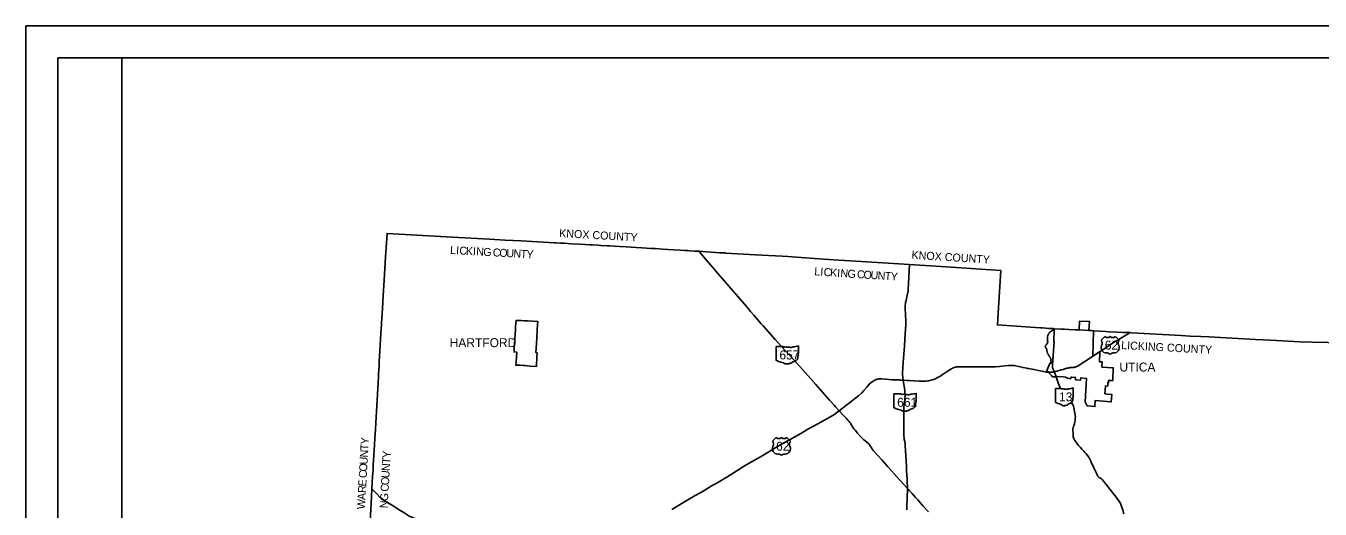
# Model space of a CAD drawing. Extents: x 1853412 to 2125412, y 679418 to 855418.
# Drawn here: x 1853412 to 2015090, y 795017 to 855418 of the extents above; entities that cross this region are included whole.
import ezdxf

# ---------------------------------------------------------------- set-up
doc = ezdxf.new("R2010")
doc.units = 0
for name, color, linetype in [('GM_X_Corporation', 7, 'Continuous'), ('GM_X_Corporation_Text', 7, 'Continuous'), ('GM_X_County', 7, 'Continuous'), ('GM_X_County_Text', 7, 'Continuous'), ('GM_X_State_Location', 7, 'Continuous'), ('GM_X_State_Route', 7, 'Continuous'), ('GM_X_State_Shield', 7, 'Continuous'), ('GM_X_US_Location', 7, 'Continuous'), ('GM_X_US_Route', 7, 'Continuous'), ('GM_X_US_Shield', 7, 'Continuous'), ('SH_Border', 7, 'Continuous'), ('SH_Cut_Line', 7, 'Continuous'), ('UT_P_Electric', 7, 'Continuous')]:
    doc.layers.add(name, color=color, linetype=linetype)

msp = doc.modelspace()

# ---------------------------------------------------------------- linework, layer by layer
at = {"layer": 'GM_X_Corporation'}
for points in [[(1914724, 814655), (1914398, 814673), (1914412, 814947), (1914420, 815224), (1914432, 815606), (1914531, 816947), (1914563, 817386), (1914595, 817823), (1914651, 818601), (1914704, 818599), (1915130, 818580), (1915208, 818576), (1915270, 818573), (1915679, 818555), (1916069, 818537), (1917358, 818478), (1917357, 818463), (1917331, 818109), (1917296, 817447), (1917280, 817170), (1917267, 816962), (1917256, 816776), (1917238, 816462), (1917230, 816341), (1917224, 816233), (1917223, 816217), (1917207, 815951), (1917187, 815616), (1917186, 815591), (1917184, 815559), (1917170, 815331), (1917162, 815184), (1917154, 815065), (1917125, 814574), (1917279, 814563), (1917277, 814507), (1917257, 814106), (1917189, 812840), (1916411, 812900), (1916348, 812905), (1915789, 812949), (1915630, 812964), (1915571, 812970), (1915140, 813012), (1915128, 812993), (1914613, 813031), (1914668, 813436)], [(1981154, 816897), (1981175, 816939), (1981192, 816964), (1981206, 816983), (1981238, 817017), (1981301, 817081), (1981398, 817177), (1981452, 817228), (1981492, 817262), (1981605, 817331), (1981628, 817344), (1981652, 817357), (1981715, 817381), (1981730, 817388), (1981736, 817397), (1981738, 817405), (1981741, 817412), (1981746, 817433), (1981742, 817466), (1981740, 817480), (1981743, 817496), (1981744, 817501), (1981746, 817515), (1981750, 817533), (1981752, 817543), (1981756, 817574), (1981870, 817569), (1983126, 817503), (1983702, 817463), (1984529, 817426), (1984709, 817415), (1984840, 817408), (1984978, 817400), (1984978, 817406), (1984970, 817421), (1985045, 818514), (1986261, 818487), (1986194, 817351), (1986529, 817328), (1986784, 817315), (1986701, 814154), (1987449, 814626), (1987568, 814701), (1987524, 813441), (1987877, 813412), (1987824, 812777), (1989249, 812678), (1989179, 811086), (1988663, 811098), (1988656, 810796), (1988626, 810826), (1988581, 810867), (1988556, 810393), (1988261, 810409), (1988203, 809429), (1988528, 809401), (1989066, 809354), (1989007, 808427), (1987000, 808604), (1986961, 807841), (1985997, 807925), (1985725, 808427), (1985892, 811352), (1985184, 811418), (1985168, 811140), (1984520, 811185), (1984536, 811454), (1984092, 811492), (1983949, 811505), (1983939, 811313), (1983720, 811361), (1983512, 811406), (1983283, 811517), (1982679, 811593), (1982111, 811563), (1981644, 811563), (1981518, 811702), (1981130, 812128), (1980942, 812333), (1981200, 812912), (1981381, 813302), (1981451, 813249), (1981464, 813380), (1981475, 813465), (1981473, 813485), (1981473, 813511), (1981470, 813528), (1981471, 813550), (1981461, 813613), (1981458, 813738), (1981458, 813755), (1981457, 813781), (1981453, 813802), (1981431, 813856), (1981424, 813873), (1981408, 813902), (1981387, 813936), (1981369, 813964), (1981340, 814006), (1981308, 814050), (1981258, 814123), (1981245, 814143), (1981217, 814189), (1981182, 814240), (1981151, 814292), (1981129, 814332), (1981097, 814386), (1981076, 814426), (1981054, 814466), (1981040, 814501), (1981029, 814528), (1981018, 814557), (1981005, 814586), (1981001, 814599), (1980988, 814633), (1980978, 814671), (1980976, 814676), (1980975, 814709), (1980973, 814725), (1980972, 814734), (1980966, 814781), (1980962, 814795), (1980960, 814803), (1980960, 814812), (1980959, 814847), (1980955, 814868), (1980955, 814871), (1980950, 814918), (1980944, 814953), (1980937, 814985), (1980930, 815003), (1980907, 815043), (1980897, 815056), (1980874, 815090), (1980857, 815111), (1980820, 815166), (1980790, 815216), (1980778, 815239), (1980769, 815264), (1980762, 815290), (1980760, 815303), (1980759, 815324), (1980759, 815344), (1980761, 815357), (1980765, 815372), (1980773, 815389), (1980784, 815406), (1980794, 815417), (1980818, 815456), (1980827, 815471), (1980858, 815512), (1980885, 815543), (1980926, 815602), (1980964, 815657), (1980979, 815678), (1980993, 815696), (1981001, 815709), (1981005, 815716), (1981013, 815737), (1981034, 815819), (1981057, 815897), (1981060, 815917), (1981060, 815938), (1981058, 815950), (1981057, 815959), (1981054, 815969), (1981049, 815983), (1981021, 816075), (1981017, 816136), (1981022, 816335), (1981027, 816546), (1981075, 816700), (1981082, 816723), (1981120, 816822), (1981138, 816864)]]:
    msp.add_lwpolyline(points, close=True, dxfattribs=at)
at = {"layer": 'GM_X_County'}
msp.add_lwpolyline([(1896383, 792786), (1896549, 795741), (1896640, 797539), (1896644, 797604), (1896728, 799113), (1896776, 799934), (1896815, 800598), (1896841, 801062), (1896877, 801716), (1896960, 803042), (1897014, 803893), (1897037, 804352), (1897400, 810815), (1897451, 811579), (1897480, 811933), (1897539, 812985), (1897563, 813419), (1897622, 814815), (1897736, 816950), (1897821, 818182), (1897828, 818257), (1897947, 820093), (1898047, 821707), (1898127, 823010), (1898165, 823653), (1898352, 826534), (1898387, 827092), (1898530, 829468), (1903006, 829212), (1906703, 828996), (1911340, 828742), (1913287, 828636), (1915271, 828536), (1919433, 828302), (1919668, 828292), (1920206, 828267), (1920580, 828244), (1920653, 828242), (1921535, 828187), (1922550, 828131), (1923280, 828086), (1923869, 828056), (1924212, 828035), (1924884, 827998), (1925241, 827975), (1926021, 827928), (1926322, 827910), (1927588, 827835), (1928412, 827800), (1929657, 827724), (1930354, 827679), (1930920, 827644), (1931539, 827608), (1932012, 827584), (1932937, 827525), (1933609, 827479), (1934356, 827436), (1935132, 827380), (1935716, 827350), (1936120, 827325), (1936311, 827314), (1936924, 827276), (1937532, 827240), (1937968, 827208), (1938444, 827185), (1939560, 827107), (1940112, 827070), (1940744, 827034), (1940804, 827028), (1944569, 826800), (1947877, 826620), (1948592, 826572), (1953053, 826265), (1955665, 826095), (1955709, 826088), (1958412, 825906), (1961146, 825748), (1963813, 825576), (1968379, 825285), (1968994, 825253), (1975184, 824851), (1974904, 820238), (1974871, 819560), (1974781, 818037), (1978930, 817778), (1980161, 817683), (1980203, 817671), (1980400, 817660), (1980833, 817636), (1981174, 817614), (1981338, 817602), (1981470, 817591), (1981520, 817588), (1981554, 817584), (1981756, 817574), (1981870, 817569), (1982739, 817527), (1985661, 817385), (1986194, 817351), (1986762, 817321), (1988299, 817219), (1988745, 817193), (1989753, 817138), (1990488, 817100), (1990798, 817083), (1990911, 817079), (1991299, 817080), (1991540, 817069), (1993052, 816987), (1997717, 816726), (1998868, 816656), (2000193, 816596), (2001220, 816537), (2001879, 816525), (2006295, 816254), (2007010, 816217), (2008903, 816117), (2012612, 815941), (2014115, 815904), (2017998, 815808)], dxfattribs=at)
at = {"layer": 'GM_X_State_Route'}
msp.add_line((1963529, 797443), (1963528, 797601), dxfattribs=at)
for points in [[(1955006, 807313), (1954560, 807817), (1954387, 808010), (1953821, 808644), (1952060, 810625), (1951435, 811327), (1950076, 812853), (1948275, 814845), (1947030, 816230), (1945501, 817914), (1945399, 818039), (1945262, 818191), (1944358, 819256), (1943952, 819717), (1943465, 820286), (1939613, 824753), (1939458, 824933), (1938398, 826163), (1937533, 827237)], [(1963430, 821326), (1963513, 821715), (1963605, 822142), (1963616, 822214), (1963623, 822411), (1963814, 825573)], [(1963334, 820969), (1963359, 821073), (1963423, 821290), (1963430, 821326)], [(1962930, 812018), (1963007, 813357), (1963154, 815429), (1963269, 816986), (1963338, 818055), (1963345, 818258), (1963345, 818442), (1963342, 818635), (1963330, 818828), (1963309, 819027), (1963280, 819603), (1963262, 819823), (1963253, 820015), (1963253, 820190), (1963257, 820302), (1963273, 820501), (1963282, 820686), (1963287, 820754), (1963315, 820887), (1963334, 820969)], [(1963019, 811123), (1962930, 811797), (1962927, 811970), (1962930, 812018)], [(1963528, 797601), (1963526, 797833), (1963505, 798311), (1963498, 798778), (1963429, 799811), (1963400, 800374), (1963371, 801045), (1963272, 802908), (1963250, 803167), (1963191, 803475), (1963149, 803715), (1963116, 803909), (1963094, 804165), (1963086, 804336), (1963102, 804880), (1963104, 806015), (1963088, 807602), (1963095, 807755), (1963100, 807877), (1963114, 808065), (1963125, 808195), (1963201, 808708), (1963229, 808914), (1963241, 809183), (1963244, 809304), (1963229, 809552), (1963196, 809878), (1963158, 810111), (1963019, 811123)], [(1963528, 797601), (1962229, 799055), (1961269, 800123), (1961053, 800359), (1960909, 800515), (1960337, 801171), (1959245, 802364), (1959032, 802659), (1958795, 803055), (1958749, 803112), (1958709, 803158), (1958615, 803245), (1958109, 803671), (1957735, 804063), (1957263, 804571), (1957032, 804827), (1956884, 804997), (1956742, 805185), (1956513, 805578), (1956414, 805759), (1956344, 805854), (1956249, 805978), (1956131, 806109), (1955931, 806325), (1955785, 806482), (1955445, 806840), (1955103, 807224), (1955006, 807313)], [(1963459, 794937), (1963468, 795229), (1963509, 796558), (1963529, 797443)], [(1966168, 794673), (1965478, 795440), (1964828, 796167), (1964564, 796455), (1964108, 796961), (1963761, 797359), (1963703, 797422), (1963528, 797601)]]:
    msp.add_lwpolyline(points, dxfattribs=at)
at = {"layer": 'GM_X_State_Shield'}
for p, q in [((1947140, 815305), (1947140, 813604)), ((1947988, 815335), (1947168, 815335)), ((1949942, 814487), (1949942, 815377)), ((1949941, 814487), (1949942, 814487)), ((1982019, 810071), (1982019, 808370)), ((1982697, 810100), (1982041, 810100)), ((1984260, 809252), (1984260, 810142)), ((1961841, 809389), (1961841, 807688)), ((1962689, 809418), (1961869, 809418)), ((1964642, 808571), (1964643, 808570)), ((1964643, 808570), (1964643, 809460)), ((1984260, 809252), (1984260, 809252))]:
    msp.add_line(p, q, dxfattribs=at)
for centre, radius, start, end in [((1982044, 810074), 26, 98.1301, 188.1301), ((1982854, 810297), 252, 231.61951, 271.11188), ((1982937, 809145), 904, 80.48669, 94.98827), ((1983142, 810083), 72.7, 219.79206, 297.10237), ((1983249, 809887), 151, 54.46668, 119.14113), ((1983444, 810156), 182, 233.85621, 294.82819), ((1983765, 809580), 478, 97.34618, 120.76885), ((1983462, 812419), 2377, 275.84447, 288.90645), ((1984235, 810146), 25, 351.86209, 97.738), ((1983595, 808767), 595, 292.30889, 8.98584), ((1984349, 808880), 169, 136.8065, 186.92959), ((1984254, 809187), 38.6, 107.94398, 210.33697), ((1984009, 809074), 232, 340.03296, 23.64957), ((1984233, 809249), 26.7, 289.60381, 7.73413), ((1982045, 808366), 26.2, 171.95839, 258.30661), ((1982049, 808540), 200, 267.33899, 280.60386), ((1982090, 808271), 72.1, 29.74838, 93.27175), ((1983000, 809800), 1716, 240.41292, 257.1985), ((1982488, 807605), 537, 47.18416, 75.83597), ((1983069, 808263), 341, 230.70037, 286.29184), ((1983266, 807675), 280, 85.69512, 111.20995), ((1983291, 808136), 182, 268.77702, 315.54927), ((1983455, 807971), 51.1, 65.75173, 132.64842), ((1983433, 808205), 192, 282.87319, 323.27711), ((1983846, 807892), 326, 94.40312, 142.57675)]:
    msp.add_arc(centre, radius, start, end, dxfattribs=at)
for centre, major_axis, start_param, end_param in [((1947172, 815309), (32.5, 0), 1.7126934, 3.2834897), ((1948183, 815532), (315, 0), 4.042523, 4.731795), ((1948288, 814380), (1130, 0), 1.4047578, 1.6578581), ((1948544, 815318), (90.8, 0), 3.8360951, 5.1854146), ((1948678, 815121), (189, 0), 0.950623, 2.079405), ((1948921, 815391), (227, 0), 4.0815608, 5.1457227), ((1949323, 814815), (598, 0), 1.6990114, 2.1078141), ((1948944, 817654), (2971, 0), 4.8143942, 5.0423688), ((1949911, 815380), (31.2, 0), 6.1411519, 7.9890352), ((1947172, 813600), (32.7, 0), 3.00124, 4.5083009), ((1947177, 813775), (250, 0), 4.6659457, 4.8974612), ((1947228, 813506), (90.1, 0), 0.5192072, 1.6278991), ((1948366, 815034), (2146, 0), 4.1959971, 4.4889607), ((1947726, 812840), (671, 0), 0.8235189, 1.3235874), ((1948730, 813370), (227, 0), 4.6910439, 5.5073738), ((1948935, 813205), (63.9, 0), 1.1475842, 2.3151517), ((1948908, 813439), (240, 0), 4.9370686, 5.64225), ((1949423, 813127), (407, 0), 1.6476453, 2.4884337), ((1949110, 814001), (743, 0), 5.1017525, 6.4400178), ((1950053, 814114), (211, 0), 2.3877238, 3.2625369), ((1949934, 814422), (48.3, 0), 1.8839779, 3.6710726), ((1949627, 814309), (290, 0), 5.9346948, 6.6959481), ((1949908, 814483), (33.4, 0), 5.05454, 6.4181714), ((1948452, 813498), (426, 0), 4.0264811, 4.9967352), ((1948699, 812909), (350, 0), 1.495662, 1.9409797), ((1961873, 809393), (32.5, 0), 1.7126934, 3.2834897), ((1962884, 809616), (315, 0), 4.042523, 4.731795), ((1962989, 808463), (1130, 0), 1.4047578, 1.6578581), ((1963245, 809401), (90.8, 0), 3.8360951, 5.1854146), ((1963379, 809205), (189, 0), 0.950623, 2.079405), ((1963623, 809474), (227, 0), 4.0815608, 5.1457227), ((1964024, 808899), (598, 0), 1.6990114, 2.1078141), ((1963645, 811737), (2971, 0), 4.8143942, 5.0423688), ((1964636, 808505), (48.3, 0), 1.8839779, 3.6710726), ((1964328, 808393), (290, 0), 5.9346948, 6.6959481), ((1964612, 809464), (31.2, 0), 6.1411519, 7.9890352), ((1964609, 808567), (33.4, 0), 5.05454, 6.4181714), ((1961873, 807684), (32.7, 0), 3.00124, 4.5083009), ((1961878, 807858), (250, 0), 4.6659457, 4.8974612), ((1961929, 807590), (90.1, 0), 0.5192072, 1.6278991), ((1963067, 809118), (2146, 0), 4.1959971, 4.4889607), ((1962427, 806923), (671, 0), 0.8235189, 1.3235874), ((1963153, 807581), (426, 0), 4.0264811, 4.9967352), ((1963400, 806993), (350, 0), 1.495662, 1.9409797), ((1963431, 807454), (227, 0), 4.6910439, 5.5073738), ((1963636, 807289), (63.9, 0), 1.1475842, 2.3151517), ((1963609, 807523), (240, 0), 4.9370686, 5.64225), ((1964125, 807210), (407, 0), 1.6476453, 2.4884337), ((1963811, 808085), (743, 0), 5.1017525, 6.4400178), ((1964754, 808198), (211, 0), 2.3877238, 3.2625369)]:
    msp.add_ellipse(centre, major_axis=major_axis, ratio=0.8, start_param=start_param, end_param=end_param, dxfattribs=at)
at = {"layer": 'GM_X_US_Route'}
for points in [[(1987497, 814650), (1988061, 815023), (1988373, 815228), (1988844, 815539), (1989282, 815827), (1989559, 816003), (1989806, 816156), (1990147, 816361), (1990822, 816769), (1991185, 816988), (1991301, 817077)], [(1981852, 812180), (1981922, 812202), (1982034, 812231), (1982202, 812276), (1982739, 812422), (1982984, 812488), (1983343, 812587), (1983459, 812618), (1983587, 812652), (1983686, 812675), (1983776, 812692), (1983881, 812705), (1984015, 812714), (1984217, 812724), (1984315, 812734), (1984410, 812749), (1984501, 812769), (1984586, 812794), (1984695, 812834), (1984774, 812871), (1984862, 812917), (1984961, 812978), (1985135, 813091), (1985381, 813254), (1986137, 813752), (1986462, 813966), (1986528, 814011)], [(1986528, 814011), (1986703, 814128), (1987101, 814387), (1987471, 814632), (1987497, 814650)], [(1963432, 811097), (1963742, 811078), (1964368, 811033), (1964942, 811012), (1965480, 810994), (1965879, 811016), (1966076, 811040), (1966178, 811054), (1966336, 811085), (1966622, 811167), (1966814, 811232), (1967105, 811353), (1967377, 811491), (1967577, 811613), (1967868, 811797), (1968511, 812226), (1968955, 812523), (1969028, 812566), (1969126, 812622), (1969183, 812649), (1969392, 812732), (1969530, 812761), (1969653, 812785), (1969789, 812800), (1970498, 812803), (1971199, 812793), (1972298, 812793), (1973319, 812801), (1974501, 812811), (1975039, 812844), (1975709, 812917), (1976068, 812952)], [(1976068, 812952), (1976094, 812954), (1976413, 812981), (1976630, 812984), (1976898, 812957), (1977605, 812814), (1977983, 812715), (1978439, 812626), (1978585, 812612)], [(1978585, 812612), (1978630, 812603), (1979385, 812451), (1980094, 812310), (1980376, 812240), (1980567, 812202), (1980776, 812164), (1980827, 812155)], [(1980827, 812155), (1980868, 812148), (1980955, 812138), (1981031, 812130)], [(1981031, 812130), (1981036, 812130), (1981131, 812125), (1981289, 812137), (1981438, 812139), (1981598, 812152), (1981705, 812153), (1981852, 812180)], [(1955006, 807313), (1955946, 808058), (1956508, 808489), (1957459, 809234), (1957823, 809535), (1958106, 809836), (1958466, 810256), (1958895, 810748), (1959075, 810897), (1959253, 811028), (1959399, 811103), (1959564, 811177), (1959664, 811211), (1959762, 811240), (1959869, 811264), (1960009, 811292), (1960211, 811298), (1960337, 811297), (1960825, 811250), (1961604, 811189), (1962182, 811168), (1962509, 811162), (1962594, 811156)], [(1962594, 811156), (1963019, 811123), (1963432, 811097)], [(1942849, 800206), (1943484, 800592), (1945185, 801563), (1946020, 802055), (1946570, 802401), (1946765, 802517), (1947092, 802713), (1947307, 802831), (1948255, 803377), (1949325, 803977), (1950409, 804587), (1950617, 804714), (1951115, 804993), (1951636, 805305), (1951725, 805355), (1952331, 805698), (1953861, 806520), (1954049, 806628), (1954332, 806798), (1955006, 807313)], [(1934099, 794969), (1934865, 795428), (1935693, 795938), (1937012, 796723), (1937657, 797051), (1937999, 797266), (1938467, 797542), (1939218, 797992), (1939627, 798234), (1940473, 798728), (1940743, 798895), (1940960, 799017)], [(1940960, 799017), (1942817, 800187), (1942849, 800206)]]:
    msp.add_lwpolyline(points, dxfattribs=at)
at = {"layer": 'GM_X_US_Shield'}
for p, q in [((1988209, 816589), (1987742, 816122)), ((1989983, 816122), (1989516, 816589)), ((1988396, 814534), (1988489, 814534)), ((1989236, 814534), (1989330, 814534)), ((1947146, 803959), (1946679, 803492)), ((1948920, 803492), (1948453, 803959)), ((1947333, 801905), (1947426, 801905)), ((1948173, 801905), (1948267, 801905))]:
    msp.add_line(p, q, dxfattribs=at)
for centre, radius, start, end in [((1988536, 816922), 467, 225.573, 314.427), ((1989189, 816922), 467, 225.573, 314.427), ((1988388, 815188), 654, 154.83192, 270.63826), ((1987206, 815747), 654, 334.54712, 35.00093), ((1989337, 815188), 654, 269.36174, 25.16808), ((1990519, 815747), 654, 144.99907, 205.45288), ((1988489, 814067), 467, 36.8699, 90), ((1989236, 814067), 467, 90, 143.1301), ((1947473, 804293), 467, 225.573, 314.427), ((1948127, 804293), 467, 225.573, 314.427), ((1947325, 802558), 654, 154.83192, 270.63826), ((1946143, 803117), 654, 334.54712, 35.00093), ((1948274, 802558), 654, 269.36174, 25.16808), ((1949456, 803117), 654, 144.99907, 205.45288), ((1947426, 801438), 467, 36.8699, 90), ((1948173, 801438), 467, 90, 143.1301)]:
    msp.add_arc(centre, radius, start, end, dxfattribs=at)
at = {"layer": 'SH_Border'}
for points in [[(1857412, 851418), (1865412, 851418), (1865412, 683418), (1857412, 683418)], [(1865412, 851418), (2121412, 851418), (2121412, 683418), (1865412, 683418)]]:
    msp.add_lwpolyline(points, close=True, dxfattribs=at)
at = {"layer": 'SH_Cut_Line'}
msp.add_lwpolyline([(1853412, 679418), (2125412, 679418), (2125412, 855418), (1853412, 855418)], close=True, dxfattribs=at)
at = {"layer": 'UT_P_Electric'}
for points in [[(1981851, 815903), (1981844, 815983), (1981834, 816146), (1981833, 816286), (1981840, 816486), (1981845, 816636), (1981854, 816812), (1981864, 817188), (1981865, 817403), (1981871, 817566)], [(1981767, 814571), (1981775, 814674), (1981793, 814979), (1981809, 815214), (1981831, 815534), (1981852, 815859), (1981851, 815903)], [(1981644, 812692), (1981638, 812732), (1981638, 812789), (1981641, 812836), (1981665, 813121), (1981693, 813512)], [(1981693, 813512), (1981697, 813568), (1981716, 813857), (1981723, 813959)], [(1981723, 813959), (1981741, 814208), (1981748, 814315)], [(1981748, 814315), (1981757, 814438), (1981767, 814571)], [(1981852, 812180), (1981724, 812493), (1981688, 812574), (1981644, 812692)], [(1982096, 811599), (1981894, 812084), (1981852, 812180)], [(1982639, 810100), (1982427, 810686), (1982112, 811561), (1982096, 811599)], [(1984513, 806588), (1984511, 806684), (1984502, 806790), (1984414, 807239), (1984330, 807662), (1984293, 807856), (1984270, 807935), (1984245, 808000), (1984207, 808054), (1984124, 808188), (1984059, 808300), (1984025, 808356)], [(1984523, 803488), (1984454, 803585), (1984363, 803743), (1984276, 803910), (1984238, 804054), (1984236, 804121), (1984220, 804612), (1984215, 804781), (1984209, 804987), (1984210, 805042), (1984216, 805108), (1984233, 805181), (1984283, 805325), (1984325, 805448), (1984391, 805676), (1984422, 805791), (1984435, 805872), (1984473, 806133), (1984493, 806304), (1984502, 806403), (1984513, 806562), (1984513, 806588)], [(1986486, 800898), (1986475, 800923), (1986310, 801280), (1986237, 801420), (1986183, 801520), (1986047, 801703), (1985868, 801912), (1985708, 802087), (1985561, 802259), (1985344, 802466), (1985317, 802526), (1985151, 802704), (1984983, 802887), (1984866, 803024), (1984680, 803281), (1984553, 803446), (1984523, 803488)], [(1990580, 794429), (1990546, 794549), (1990467, 794797), (1990362, 795120), (1990206, 795596), (1990131, 795818), (1989717, 796353), (1988977, 797305), (1988373, 798080), (1987893, 798681), (1987836, 798754), (1987761, 798815), (1987673, 798874), (1987499, 798978), (1987396, 799052), (1987331, 799125), (1987274, 799220), (1987138, 799493), (1986804, 800187), (1986486, 800898)], [(1896641, 797536), (1897200, 796952), (1897643, 796497), (1897757, 796410), (1897911, 796297), (1898148, 796145), (1898807, 795733), (1899294, 795420), (1900041, 794949), (1900533, 794641), (1900757, 794500), (1900989, 794344), (1901226, 794196), (1901430, 794089), (1902072, 793798), (1902386, 793656), (1902948, 793385), (1903111, 793308)]]:
    msp.add_lwpolyline(points, dxfattribs=at)

# ---------------------------------------------------------------- texts
at = {"layer": 'GM_X_Corporation_Text'}
for s, p in [('HARTFORD', (1906355, 815263)), ('UTICA', (1990023, 812214))]:
    msp.add_text(s, height=1120, rotation=0.00001, dxfattribs=at).set_placement(p)
at = {"layer": 'GM_X_County_Text'}
for s, rotation, p in [('KNOX COUNTY', 356.77031, (1920006, 829027)), ('L', 356.47372, (1906378, 826919)), ('I', 356.80495, (1907131, 826873)), ('C', 356.86014, (1907540, 826850)), ('K', 356.88174, (1908354, 826805)), ('I', 356.88612, (1909237, 826757)), ('N', 356.88946, (1909645, 826735)), ('G', 356.88852, (1910529, 826687)), ('C', 356.88774, (1911715, 826622)), ('O', 356.88848, (1912528, 826578)), ('U', 356.88852, (1913411, 826530)), ('N', 356.88834, (1914294, 826482)), ('T', 356.88841, (1915177, 826434)), ('Y', 356.88834, (1915924, 826394)), ('KNOX COUNTY', 356.32859, (1964021, 826320)), ('L', 356.12071, (1951879, 824250)), ('I', 356.12268, (1952625, 824199)), ('C', 356.11482, (1953033, 824172)), ('K', 356.09868, (1953845, 824117)), ('I', 356.06743, (1954728, 824057)), ('N', 356.02347, (1955136, 824028)), ('G', 356.39822, (1956025, 823967)), ('C', 356.42437, (1957211, 823892)), ('O', 356.42451, (1958024, 823841)), ('U', 356.42519, (1958906, 823786)), ('N', 356.4256, (1959789, 823731)), ('T', 356.42512, (1960672, 823676)), ('Y', 356.4256, (1961418, 823629)), ('LICKING COUNTY', 356.91356, (1990219, 815033)), ('Y', 86.65869, (1896221, 803081)), ('N', 86.78487, (1896129, 801451)), ('T', 86.7738, (1896179, 802334)), ('Y', 86.7617, (1898953, 801385)), ('O', 86.78487, (1896030, 799685)), ('U', 86.78397, (1896080, 800568)), ('N', 86.76079, (1898860, 799755)), ('T', 86.76129, (1898910, 800638)), ('C', 86.784, (1895984, 798873)), ('O', 86.72773, (1898760, 797989)), ('U', 86.75497, (1898810, 798872)), ('R', 86.78455, (1895880, 797010)), ('E', 86.78421, (1895925, 797823)), ('C', 86.44149, (1898709, 797171)), ('W', 86.78406, (1895765, 794976)), ('A', 86.78397, (1895830, 796127)), ('N', 86.9254, (1898597, 795104)), ('G', 86.89562, (1898645, 795987))]:
    msp.add_text(s, height=1000, rotation=rotation, dxfattribs=at).set_placement(p)
at = {"layer": 'GM_X_State_Location'}
for s, p in [('657', (1948378, 814158)), ('13', (1982812, 809067)), ('661', (1962818, 808337))]:
    msp.add_text(s, height=1, rotation=0.00001, dxfattribs=at).set_placement(p)
for s, p in [('s', (1948731, 814231)), ('r', (1948731, 814231)), ('s', (1963171, 808410)), ('r', (1963171, 808410)), ('s', (1983064, 809140)), ('r', (1983064, 809140))]:
    msp.add_text(s, height=1, dxfattribs=at).set_placement(p)
at = {"layer": 'GM_X_State_Shield'}
for s, p in [('657', (1947547, 813724)), ('661', (1962254, 807808)), ('13', (1982475, 808490))]:
    msp.add_text(s, height=1120.7, dxfattribs=at).set_placement(p)
at = {"layer": 'GM_X_US_Location'}
for p in [(1988796, 815456), (1970210, 812596), (1947559, 802885)]:
    msp.add_text('62', height=1, rotation=0.00001, dxfattribs=at).set_placement(p)
for s, p in [('0', (1989002, 815663)), ('/', (1989002, 815663)), ('0', (1970417, 812803)), ('/', (1970417, 812803)), ('0', (1947766, 803092)), ('/', (1947766, 803092))]:
    msp.add_text(s, height=1, dxfattribs=at).set_placement(p)
at = {"layer": 'GM_X_US_Shield'}
for p in [(1988193, 814955), (1947130, 802325)]:
    msp.add_text('62', height=1120.7, dxfattribs=at).set_placement(p)

doc.saveas('drawing.dxf')
